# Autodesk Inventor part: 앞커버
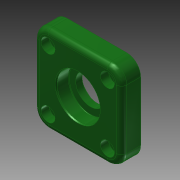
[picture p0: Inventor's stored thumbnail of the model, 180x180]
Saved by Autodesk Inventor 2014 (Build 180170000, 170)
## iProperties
Created: 2018-07
Part Number: 앞커버
Material: 알루미늄 6061
Document SubType Name: Modeling
Designer: mduedu
Density: 1 g/cm^3
Appearance: 매끄러움 - 짙은 산림 녹색
Author: mduedu
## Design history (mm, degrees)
sketch "스케치1"
  geometry: C1 r 16 at (0, 0); 1 further point
  constraints: 1 centre point, 1 coincident
  dimensions: "d0" = 32 diameter of C1
extrude "돌출1" new body sketch "스케치1" distance "d1" = 3; taper "d2" = 0 deg
sketch "스케치2"
  geometry: L1 (-25, -25)-(25, -25); L2 (25, -25)-(25, 25); L3 (25, 25)-(-25, 25); L4 (-25, 25)-(-25, -25); L5 (-25, -25)-(25, 25); L6 (25, -25)-(-25, 25); 1 further point
  constraints: 12 end point, 2 midpoint, 2 parallel, 1 horizontal, 1 perpendicular
  dimensions: "d3" = 50 distance of L3.end L2.end; "d4" = 50 distance of L2.end L1.end
extrude "돌출2" join sketch "스케치2" distance "d5" = 11; taper "d6" = 0 deg
hole "구멍1" diameter "d9" = 25; stored, may be unused: countersink angle "d13" = 90 deg, drill point angle "d15" = 0 deg; dims "d7" = 10, "d8" = 10, "d10" = 6, "d11" = 4, "d12" = 2, "d14" = 3
sketch "스케치3"
  geometry: C1 r 12.5 at (0, 0); 1 further point
  constraints: 1 centre point, 1 coincident
  dimensions: "d16" = 25 diameter of C1
extrude "돌출3" cut sketch "스케치3" distance "d17" = 7.3; taper "d18" = 0 deg
sketch "스케치4"
  geometry: C1 r 8.5 at (0, 0); 1 further point
  constraints: 1 centre point, 1 coincident
  dimensions: "d19" = 17 diameter of C1
extrude "돌출4" cut sketch "스케치4" stored distance "d20" = 7.3; taper "d21" = 0 deg
chamfer "모따기1" distance "d22" = 0.7; stored, may be unused: second distance "d23" = 2, angle "d24" = 30 deg
fillet "모깎기1" dims "d25" = 0.3
fillet "모깎기2" dims "d26" = 3
fillet "모깎기3" dims "d27" = 8
sketch "스케치5"
  geometry: L1 (25, -17)-(25, 17) reference; L2 (17, 25)-(-17, 25) reference; L3 (-25, 17)-(-25, -17) reference; L4 (-17, -25)-(17, -25) reference; C1 r 12.904 at (0, 0) reference; A1 r 8 centre (17, -17) between (17, -25) and (25, -17) reference; A2 r 8 centre (17, 17) between (25, 17) and (17, 25) reference; A3 r 8 centre (-17, 17) between (-17, 25) and (-25, 17) reference; A4 r 8 centre (-17, -17) between (-25, -17) and (-17, -25) reference; 5 further points
  constraints: 4 coincident
hole "구멍2" sketch "스케치5" at (-17, 17), (17, 17), (17, -17), (-17, -17) diameter "d28" = 4.5; stored, may be unused: countersink angle "d32" = 90 deg, drill point angle "d34" = 0 deg; dims "d29" = 6, "d30" = 8, "d31" = 4.6, "d33" = 3
fillet "모깎기4" dims "d35" = 3
chamfer "모따기2" distance "d36" = 1; stored, may be unused: second distance "d37" = 2, angle "d38" = 45 deg
node "솔리드1"
node "투영된 루프1"
